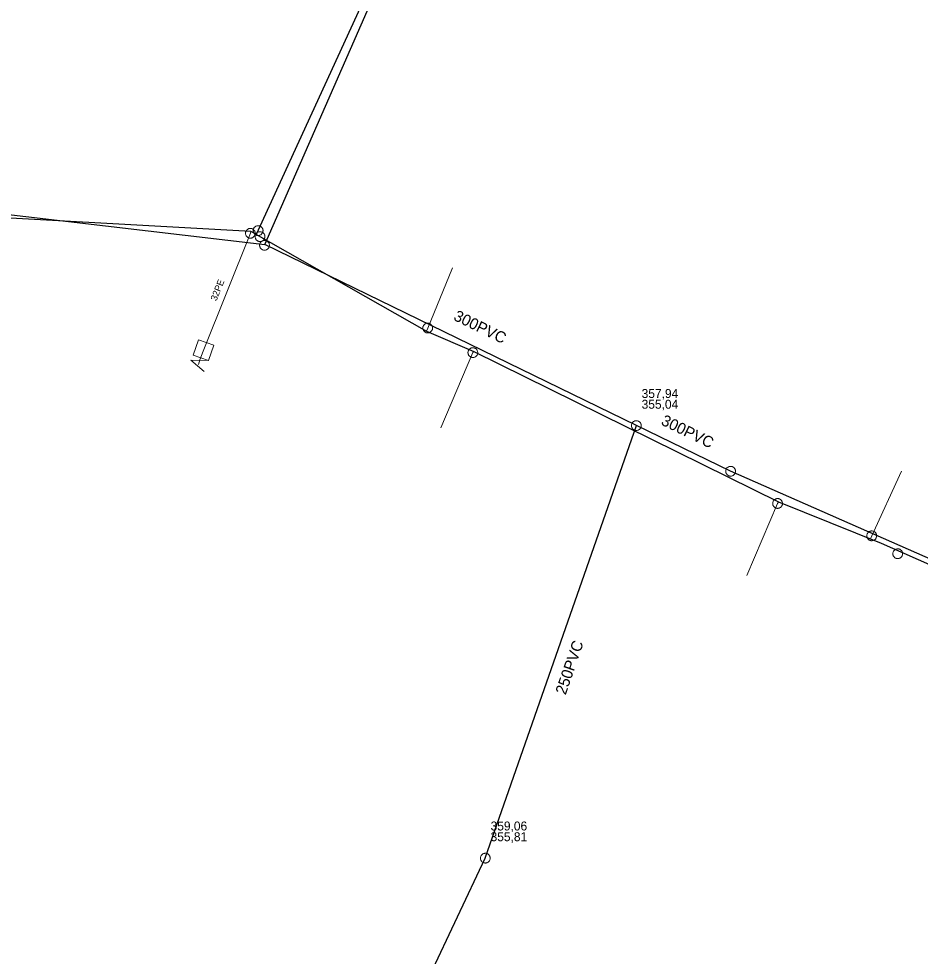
# Model space of a CAD drawing. Extents: x -741806 to -738704, y -1059275 to -1055387.
# Drawn here: x -740647.7 to -740567.1, y -1058133.8 to -1058050 of the extents above; entities that cross this region are included whole.
import ezdxf

# ---------------------------------------------------------------- set-up
doc = ezdxf.new("R2010")
doc.units = 0
doc.header["$LTSCALE"] = 0.4
for name, color, linetype, lineweight in [('2', 7, 'Continuous', 25), ('21', 7, 'Continuous', 13), ('3', 7, 'Continuous', 13), ('51', 7, 'Continuous', 13), ('52', 7, 'Continuous', 25), ('6', 7, 'Continuous', 13), ('60', 7, 'Continuous', 13)]:
    doc.layers.add(name, color=color, linetype=linetype, lineweight=lineweight)
doc.layers.add('5', color=7, linetype='Continuous')
doc.layers.add('54', color=7, linetype='Continuous')

msp = doc.modelspace()

# ---------------------------------------------------------------- linework, layer by layer
at = {"layer": '2'}
for p, q in [((-740584.07, -1058090.47), (-740592.5, -1058086.389)), ((-740538.35, -1058110.56), (-740584.07, -1058090.47))]:
    msp.add_line(p, q, dxfattribs=at)
for points in [[(-740592.5, -1058086.389), (-740625.71, -1058070.179), (-740593.93, -1057997.629)], [(-740824.89, -1058051.27), (-740778.35, -1058055.46), (-740728.07, -1058059.94), (-740708.829, -1058061.48), (-740678.949, -1058063.95), (-740625.71, -1058070.179)], [(-740583.26, -1058185.25), (-740598.636, -1058178.666), (-740610.313, -1058173.665), (-740625.809, -1058167.03), (-740606.009, -1058125.064), (-740592.5, -1058086.389)]]:
    msp.add_lwpolyline(points, dxfattribs=at)
at = {"layer": '21'}
for points in [[(-740626.965, -1058069.033), (-740627.02, -1058069.19), (-740631.25, -1058079.72), (-740631.527, -1058080.499), (-740631.654, -1058080.922)], [(-740611.274, -1058077.928), (-740611.16, -1058077.659), (-740608.947, -1058072.284)], [(-740607.048, -1058079.747), (-740607.12, -1058079.86), (-740609.973, -1058086.591)], [(-740571.566, -1058096.51), (-740571.449, -1058096.24), (-740568.795, -1058090.463)], [(-740579.795, -1058093.213), (-740579.87, -1058093.35), (-740582.627, -1058099.791)]]:
    msp.add_lwpolyline(points, dxfattribs=at)
at = {"layer": '3'}
for points in [[(-740625.317, -1058070.31), (-740625.315, -1058070.265), (-740625.317, -1058070.22), (-740625.324, -1058070.174), (-740625.336, -1058070.13), (-740625.352, -1058070.087), (-740625.373, -1058070.046), (-740625.398, -1058070.008), (-740625.426, -1058069.971), (-740625.459, -1058069.94), (-740625.494, -1058069.911), (-740625.533, -1058069.885), (-740625.574, -1058069.864), (-740625.616, -1058069.848), (-740625.66, -1058069.835), (-740625.705, -1058069.829), (-740625.751, -1058069.826), (-740625.797, -1058069.829), (-740625.842, -1058069.835), (-740625.887, -1058069.847), (-740625.93, -1058069.864), (-740625.97, -1058069.884), (-740626.008, -1058069.908), (-740626.044, -1058069.938), (-740626.077, -1058069.969), (-740626.106, -1058070.005), (-740626.13, -1058070.044), (-740626.152, -1058070.084), (-740626.168, -1058070.127), (-740626.18, -1058070.171), (-740626.187, -1058070.217), (-740626.19, -1058070.262), (-740626.188, -1058070.307), (-740626.181, -1058070.353), (-740626.169, -1058070.398), (-740626.153, -1058070.44), (-740626.132, -1058070.481), (-740626.107, -1058070.519), (-740626.078, -1058070.556), (-740626.046, -1058070.587), (-740626.011, -1058070.616), (-740625.973, -1058070.642), (-740625.932, -1058070.663), (-740625.889, -1058070.68), (-740625.845, -1058070.692), (-740625.8, -1058070.698), (-740625.754, -1058070.701), (-740625.708, -1058070.699), (-740625.663, -1058070.692), (-740625.619, -1058070.68), (-740625.576, -1058070.663), (-740625.535, -1058070.643), (-740625.496, -1058070.619), (-740625.461, -1058070.589), (-740625.428, -1058070.558), (-740625.399, -1058070.522), (-740625.374, -1058070.483), (-740625.354, -1058070.443), (-740625.337, -1058070.4), (-740625.325, -1058070.356), (-740625.317, -1058070.311)], [(-740592.894, -1058086.197), (-740592.91, -1058086.239), (-740592.924, -1058086.283), (-740592.933, -1058086.328), (-740592.936, -1058086.373), (-740592.935, -1058086.419), (-740592.93, -1058086.465), (-740592.919, -1058086.509), (-740592.905, -1058086.553), (-740592.884, -1058086.594), (-740592.861, -1058086.633), (-740592.833, -1058086.67), (-740592.802, -1058086.704), (-740592.767, -1058086.733), (-740592.73, -1058086.76), (-740592.69, -1058086.781), (-740592.647, -1058086.8), (-740592.603, -1058086.812), (-740592.559, -1058086.821), (-740592.513, -1058086.825), (-740592.467, -1058086.824), (-740592.422, -1058086.818), (-740592.378, -1058086.808), (-740592.334, -1058086.792), (-740592.293, -1058086.774), (-740592.253, -1058086.749), (-740592.217, -1058086.721), (-740592.184, -1058086.691), (-740592.153, -1058086.656), (-740592.127, -1058086.618), (-740592.105, -1058086.578), (-740592.088, -1058086.536), (-740592.074, -1058086.493), (-740592.066, -1058086.447), (-740592.062, -1058086.401), (-740592.063, -1058086.356), (-740592.068, -1058086.31), (-740592.079, -1058086.266), (-740592.094, -1058086.222), (-740592.114, -1058086.181), (-740592.137, -1058086.142), (-740592.165, -1058086.106), (-740592.196, -1058086.072), (-740592.23, -1058086.042), (-740592.268, -1058086.016), (-740592.308, -1058085.994), (-740592.351, -1058085.976), (-740592.394, -1058085.962), (-740592.439, -1058085.954), (-740592.485, -1058085.95), (-740592.531, -1058085.951), (-740592.576, -1058085.957), (-740592.621, -1058085.967), (-740592.664, -1058085.983), (-740592.706, -1058086.002), (-740592.745, -1058086.026), (-740592.782, -1058086.054), (-740592.814, -1058086.084), (-740592.845, -1058086.12), (-740592.871, -1058086.157), (-740592.893, -1058086.196)], [(-740584.47, -1058090.293), (-740584.486, -1058090.335), (-740584.497, -1058090.379), (-740584.504, -1058090.425), (-740584.507, -1058090.47), (-740584.504, -1058090.516), (-740584.497, -1058090.562), (-740584.484, -1058090.606), (-740584.468, -1058090.649), (-740584.447, -1058090.689), (-740584.422, -1058090.727), (-740584.393, -1058090.763), (-740584.36, -1058090.796), (-740584.324, -1058090.823), (-740584.286, -1058090.849), (-740584.245, -1058090.869), (-740584.202, -1058090.886), (-740584.158, -1058090.897), (-740584.113, -1058090.904), (-740584.067, -1058090.906), (-740584.021, -1058090.903), (-740583.976, -1058090.896), (-740583.933, -1058090.884), (-740583.889, -1058090.867), (-740583.849, -1058090.847), (-740583.81, -1058090.821), (-740583.775, -1058090.792), (-740583.743, -1058090.76), (-740583.714, -1058090.724), (-740583.689, -1058090.685), (-740583.669, -1058090.644), (-740583.653, -1058090.602), (-740583.641, -1058090.558), (-740583.634, -1058090.512), (-740583.632, -1058090.466), (-740583.634, -1058090.421), (-740583.641, -1058090.375), (-740583.654, -1058090.332), (-740583.671, -1058090.288), (-740583.692, -1058090.248), (-740583.716, -1058090.21), (-740583.745, -1058090.174), (-740583.778, -1058090.142), (-740583.813, -1058090.113), (-740583.852, -1058090.088), (-740583.893, -1058090.068), (-740583.936, -1058090.051), (-740583.98, -1058090.04), (-740584.025, -1058090.033), (-740584.071, -1058090.031), (-740584.117, -1058090.034), (-740584.162, -1058090.042), (-740584.206, -1058090.053), (-740584.249, -1058090.07), (-740584.29, -1058090.09), (-740584.328, -1058090.116), (-740584.364, -1058090.145), (-740584.395, -1058090.177), (-740584.425, -1058090.214), (-740584.449, -1058090.252), (-740584.47, -1058090.292)], [(-740605.821, -1058124.668), (-740605.863, -1058124.651), (-740605.907, -1058124.638), (-740605.953, -1058124.63), (-740605.997, -1058124.626), (-740606.043, -1058124.628), (-740606.089, -1058124.634), (-740606.133, -1058124.645), (-740606.177, -1058124.66), (-740606.218, -1058124.681), (-740606.256, -1058124.704), (-740606.293, -1058124.732), (-740606.327, -1058124.764), (-740606.355, -1058124.799), (-740606.382, -1058124.836), (-740606.403, -1058124.877), (-740606.421, -1058124.92), (-740606.433, -1058124.964), (-740606.442, -1058125.008), (-740606.445, -1058125.054), (-740606.443, -1058125.1), (-740606.437, -1058125.146), (-740606.427, -1058125.189), (-740606.411, -1058125.233), (-740606.392, -1058125.274), (-740606.367, -1058125.313), (-740606.338, -1058125.349), (-740606.308, -1058125.382), (-740606.272, -1058125.412), (-740606.234, -1058125.438), (-740606.194, -1058125.459), (-740606.152, -1058125.477), (-740606.108, -1058125.49), (-740606.063, -1058125.498), (-740606.016, -1058125.501), (-740605.972, -1058125.5), (-740605.926, -1058125.494), (-740605.882, -1058125.483), (-740605.838, -1058125.467), (-740605.798, -1058125.447), (-740605.759, -1058125.424), (-740605.722, -1058125.395), (-740605.689, -1058125.364), (-740605.659, -1058125.329), (-740605.633, -1058125.291), (-740605.612, -1058125.251), (-740605.594, -1058125.208), (-740605.581, -1058125.164), (-740605.573, -1058125.12), (-740605.57, -1058125.073), (-740605.572, -1058125.027), (-740605.578, -1058124.982), (-740605.588, -1058124.938), (-740605.604, -1058124.895), (-740605.624, -1058124.854), (-740605.648, -1058124.814), (-740605.676, -1058124.778), (-740605.708, -1058124.746), (-740605.743, -1058124.715), (-740605.781, -1058124.69), (-740605.82, -1058124.668)]]:
    msp.add_lwpolyline(points, dxfattribs=at)
at = {"layer": '51'}
for points in [[(-740626.583, -1058069.19), (-740626.585, -1058069.145), (-740626.592, -1058069.1), (-740626.604, -1058069.055), (-740626.62, -1058069.013), (-740626.641, -1058068.972), (-740626.666, -1058068.933), (-740626.695, -1058068.898), (-740626.727, -1058068.865), (-740626.763, -1058068.837), (-740626.801, -1058068.812), (-740626.842, -1058068.791), (-740626.885, -1058068.774), (-740626.929, -1058068.762), (-740626.974, -1058068.755), (-740627.02, -1058068.753), (-740627.066, -1058068.755), (-740627.111, -1058068.762), (-740627.155, -1058068.774), (-740627.198, -1058068.791), (-740627.239, -1058068.812), (-740627.277, -1058068.837), (-740627.313, -1058068.865), (-740627.345, -1058068.898), (-740627.374, -1058068.933), (-740627.399, -1058068.972), (-740627.42, -1058069.013), (-740627.436, -1058069.055), (-740627.448, -1058069.1), (-740627.455, -1058069.145), (-740627.458, -1058069.191), (-740627.455, -1058069.236), (-740627.448, -1058069.281), (-740627.436, -1058069.326), (-740627.42, -1058069.368), (-740627.399, -1058069.409), (-740627.374, -1058069.448), (-740627.345, -1058069.483), (-740627.313, -1058069.516), (-740627.277, -1058069.544), (-740627.239, -1058069.569), (-740627.198, -1058069.59), (-740627.155, -1058069.607), (-740627.111, -1058069.618), (-740627.066, -1058069.626), (-740627.02, -1058069.628), (-740626.974, -1058069.626), (-740626.929, -1058069.618), (-740626.885, -1058069.607), (-740626.842, -1058069.59), (-740626.801, -1058069.569), (-740626.763, -1058069.544), (-740626.727, -1058069.516), (-740626.695, -1058069.483), (-740626.666, -1058069.448), (-740626.641, -1058069.409), (-740626.62, -1058069.368), (-740626.604, -1058069.326), (-740626.592, -1058069.281), (-740626.585, -1058069.236), (-740626.583, -1058069.191)], [(-740626.519, -1058069.341), (-740626.477, -1058069.359), (-740626.434, -1058069.373), (-740626.388, -1058069.382), (-740626.344, -1058069.386), (-740626.298, -1058069.386), (-740626.251, -1058069.381), (-740626.207, -1058069.37), (-740626.163, -1058069.356), (-740626.122, -1058069.337), (-740626.083, -1058069.314), (-740626.046, -1058069.286), (-740626.012, -1058069.255), (-740625.981, -1058069.221), (-740625.955, -1058069.184), (-740625.933, -1058069.144), (-740625.914, -1058069.102), (-740625.9, -1058069.058), (-740625.891, -1058069.014), (-740625.887, -1058068.968), (-740625.888, -1058068.922), (-740625.893, -1058068.876), (-740625.902, -1058068.832), (-740625.918, -1058068.788), (-740625.936, -1058068.747), (-740625.96, -1058068.707), (-740625.987, -1058068.67), (-740626.018, -1058068.637), (-740626.053, -1058068.606), (-740626.09, -1058068.58), (-740626.13, -1058068.557), (-740626.171, -1058068.539), (-740626.215, -1058068.526), (-740626.26, -1058068.516), (-740626.305, -1058068.512), (-740626.351, -1058068.512), (-740626.397, -1058068.517), (-740626.442, -1058068.528), (-740626.485, -1058068.542), (-740626.526, -1058068.562), (-740626.566, -1058068.584), (-740626.603, -1058068.612), (-740626.637, -1058068.643), (-740626.667, -1058068.677), (-740626.694, -1058068.714), (-740626.716, -1058068.754), (-740626.735, -1058068.796), (-740626.748, -1058068.84), (-740626.757, -1058068.884), (-740626.761, -1058068.931), (-740626.761, -1058068.977), (-740626.755, -1058069.022), (-740626.746, -1058069.066), (-740626.731, -1058069.11), (-740626.713, -1058069.151), (-740626.689, -1058069.191), (-740626.661, -1058069.228), (-740626.631, -1058069.261), (-740626.596, -1058069.292), (-740626.559, -1058069.318), (-740626.519, -1058069.34)], [(-740625.716, -1058069.504), (-740625.716, -1058069.459), (-740625.722, -1058069.413), (-740625.732, -1058069.368), (-740625.747, -1058069.326), (-740625.766, -1058069.284), (-740625.79, -1058069.244), (-740625.818, -1058069.208), (-740625.849, -1058069.174), (-740625.884, -1058069.145), (-740625.921, -1058069.119), (-740625.961, -1058069.096), (-740626.004, -1058069.078), (-740626.047, -1058069.064), (-740626.092, -1058069.056), (-740626.138, -1058069.052), (-740626.184, -1058069.053), (-740626.229, -1058069.058), (-740626.273, -1058069.069), (-740626.317, -1058069.084), (-740626.359, -1058069.104), (-740626.398, -1058069.128), (-740626.434, -1058069.154), (-740626.468, -1058069.186), (-740626.498, -1058069.22), (-740626.524, -1058069.258), (-740626.546, -1058069.299), (-740626.564, -1058069.34), (-740626.577, -1058069.385), (-740626.586, -1058069.429), (-740626.59, -1058069.475), (-740626.589, -1058069.52), (-740626.583, -1058069.566), (-740626.573, -1058069.611), (-740626.558, -1058069.653), (-740626.539, -1058069.695), (-740626.515, -1058069.735), (-740626.487, -1058069.771), (-740626.456, -1058069.805), (-740626.421, -1058069.834), (-740626.384, -1058069.86), (-740626.344, -1058069.883), (-740626.301, -1058069.901), (-740626.258, -1058069.914), (-740626.213, -1058069.923), (-740626.167, -1058069.927), (-740626.121, -1058069.926), (-740626.076, -1058069.92), (-740626.032, -1058069.91), (-740625.988, -1058069.895), (-740625.946, -1058069.875), (-740625.908, -1058069.851), (-740625.871, -1058069.825), (-740625.838, -1058069.793), (-740625.807, -1058069.759), (-740625.781, -1058069.721), (-740625.759, -1058069.68), (-740625.741, -1058069.639), (-740625.728, -1058069.594), (-740625.719, -1058069.55), (-740625.716, -1058069.505)], [(-740610.723, -1058077.659), (-740610.725, -1058077.614), (-740610.732, -1058077.569), (-740610.744, -1058077.524), (-740610.76, -1058077.482), (-740610.781, -1058077.441), (-740610.806, -1058077.402), (-740610.835, -1058077.367), (-740610.867, -1058077.334), (-740610.903, -1058077.306), (-740610.941, -1058077.281), (-740610.982, -1058077.26), (-740611.025, -1058077.243), (-740611.069, -1058077.231), (-740611.114, -1058077.224), (-740611.16, -1058077.222), (-740611.206, -1058077.224), (-740611.251, -1058077.231), (-740611.295, -1058077.243), (-740611.338, -1058077.26), (-740611.379, -1058077.281), (-740611.417, -1058077.306), (-740611.453, -1058077.334), (-740611.485, -1058077.367), (-740611.514, -1058077.402), (-740611.539, -1058077.441), (-740611.56, -1058077.482), (-740611.576, -1058077.524), (-740611.588, -1058077.569), (-740611.595, -1058077.614), (-740611.598, -1058077.66), (-740611.595, -1058077.705), (-740611.588, -1058077.75), (-740611.576, -1058077.795), (-740611.56, -1058077.837), (-740611.539, -1058077.878), (-740611.514, -1058077.917), (-740611.485, -1058077.952), (-740611.453, -1058077.985), (-740611.417, -1058078.013), (-740611.379, -1058078.038), (-740611.338, -1058078.059), (-740611.295, -1058078.076), (-740611.251, -1058078.087), (-740611.206, -1058078.095), (-740611.16, -1058078.097), (-740611.114, -1058078.095), (-740611.069, -1058078.087), (-740611.025, -1058078.076), (-740610.982, -1058078.059), (-740610.941, -1058078.038), (-740610.903, -1058078.013), (-740610.867, -1058077.985), (-740610.835, -1058077.952), (-740610.806, -1058077.917), (-740610.781, -1058077.878), (-740610.76, -1058077.837), (-740610.744, -1058077.795), (-740610.732, -1058077.75), (-740610.725, -1058077.705), (-740610.723, -1058077.66)], [(-740606.718, -1058080.033), (-740606.702, -1058079.991), (-740606.691, -1058079.947), (-740606.684, -1058079.901), (-740606.682, -1058079.856), (-740606.685, -1058079.81), (-740606.693, -1058079.764), (-740606.706, -1058079.72), (-740606.722, -1058079.677), (-740606.744, -1058079.637), (-740606.769, -1058079.599), (-740606.798, -1058079.564), (-740606.831, -1058079.531), (-740606.867, -1058079.503), (-740606.905, -1058079.479), (-740606.947, -1058079.459), (-740606.99, -1058079.442), (-740607.034, -1058079.431), (-740607.079, -1058079.424), (-740607.125, -1058079.423), (-740607.171, -1058079.426), (-740607.216, -1058079.434), (-740607.26, -1058079.446), (-740607.303, -1058079.463), (-740607.343, -1058079.484), (-740607.382, -1058079.51), (-740607.417, -1058079.539), (-740607.448, -1058079.571), (-740607.477, -1058079.608), (-740607.501, -1058079.647), (-740607.522, -1058079.688), (-740607.537, -1058079.73), (-740607.549, -1058079.774), (-740607.556, -1058079.82), (-740607.557, -1058079.865), (-740607.554, -1058079.911), (-740607.547, -1058079.957), (-740607.534, -1058080), (-740607.518, -1058080.043), (-740607.496, -1058080.083), (-740607.471, -1058080.121), (-740607.441, -1058080.157), (-740607.409, -1058080.19), (-740607.373, -1058080.217), (-740607.334, -1058080.242), (-740607.293, -1058080.262), (-740607.25, -1058080.279), (-740607.205, -1058080.289), (-740607.161, -1058080.296), (-740607.114, -1058080.298), (-740607.069, -1058080.295), (-740607.024, -1058080.287), (-740606.98, -1058080.275), (-740606.937, -1058080.258), (-740606.897, -1058080.237), (-740606.858, -1058080.211), (-740606.823, -1058080.182), (-740606.791, -1058080.149), (-740606.763, -1058080.113), (-740606.738, -1058080.074), (-740606.719, -1058080.034)], [(-740580.08, -1058093.733), (-740580.039, -1058093.752), (-740579.997, -1058093.768), (-740579.951, -1058093.779), (-740579.907, -1058093.785), (-740579.861, -1058093.786), (-740579.814, -1058093.783), (-740579.77, -1058093.775), (-740579.726, -1058093.762), (-740579.684, -1058093.744), (-740579.644, -1058093.723), (-740579.605, -1058093.697), (-740579.57, -1058093.667), (-740579.538, -1058093.635), (-740579.51, -1058093.598), (-740579.487, -1058093.559), (-740579.466, -1058093.518), (-740579.451, -1058093.475), (-740579.44, -1058093.431), (-740579.434, -1058093.385), (-740579.433, -1058093.339), (-740579.437, -1058093.293), (-740579.444, -1058093.248), (-740579.458, -1058093.204), (-740579.475, -1058093.162), (-740579.497, -1058093.121), (-740579.523, -1058093.083), (-740579.552, -1058093.049), (-740579.585, -1058093.017), (-740579.622, -1058092.989), (-740579.66, -1058092.965), (-740579.701, -1058092.946), (-740579.744, -1058092.93), (-740579.789, -1058092.919), (-740579.834, -1058092.913), (-740579.88, -1058092.912), (-740579.926, -1058092.915), (-740579.971, -1058092.923), (-740580.015, -1058092.936), (-740580.057, -1058092.954), (-740580.097, -1058092.975), (-740580.135, -1058093.001), (-740580.171, -1058093.031), (-740580.202, -1058093.064), (-740580.23, -1058093.1), (-740580.254, -1058093.139), (-740580.274, -1058093.18), (-740580.289, -1058093.224), (-740580.301, -1058093.267), (-740580.306, -1058093.313), (-740580.308, -1058093.359), (-740580.304, -1058093.405), (-740580.297, -1058093.45), (-740580.283, -1058093.494), (-740580.266, -1058093.536), (-740580.244, -1058093.577), (-740580.218, -1058093.615), (-740580.189, -1058093.649), (-740580.155, -1058093.681), (-740580.119, -1058093.709), (-740580.081, -1058093.732)], [(-740571.012, -1058096.24), (-740571.014, -1058096.195), (-740571.021, -1058096.15), (-740571.033, -1058096.105), (-740571.049, -1058096.063), (-740571.07, -1058096.022), (-740571.095, -1058095.983), (-740571.124, -1058095.948), (-740571.156, -1058095.915), (-740571.192, -1058095.887), (-740571.23, -1058095.862), (-740571.271, -1058095.841), (-740571.314, -1058095.824), (-740571.358, -1058095.812), (-740571.403, -1058095.805), (-740571.449, -1058095.803), (-740571.495, -1058095.805), (-740571.54, -1058095.812), (-740571.584, -1058095.824), (-740571.627, -1058095.841), (-740571.668, -1058095.862), (-740571.706, -1058095.887), (-740571.742, -1058095.915), (-740571.774, -1058095.948), (-740571.803, -1058095.983), (-740571.828, -1058096.022), (-740571.849, -1058096.063), (-740571.865, -1058096.105), (-740571.877, -1058096.15), (-740571.884, -1058096.195), (-740571.887, -1058096.241), (-740571.884, -1058096.286), (-740571.877, -1058096.331), (-740571.865, -1058096.376), (-740571.849, -1058096.418), (-740571.828, -1058096.459), (-740571.803, -1058096.498), (-740571.774, -1058096.533), (-740571.742, -1058096.566), (-740571.706, -1058096.594), (-740571.668, -1058096.619), (-740571.627, -1058096.64), (-740571.584, -1058096.657), (-740571.54, -1058096.668), (-740571.495, -1058096.676), (-740571.449, -1058096.678), (-740571.403, -1058096.676), (-740571.358, -1058096.668), (-740571.314, -1058096.657), (-740571.271, -1058096.64), (-740571.23, -1058096.619), (-740571.192, -1058096.594), (-740571.156, -1058096.566), (-740571.124, -1058096.533), (-740571.095, -1058096.498), (-740571.07, -1058096.459), (-740571.049, -1058096.418), (-740571.033, -1058096.376), (-740571.021, -1058096.331), (-740571.014, -1058096.286), (-740571.012, -1058096.241)], [(-740568.69, -1058097.842), (-740568.691, -1058097.797), (-740568.699, -1058097.752), (-740568.711, -1058097.707), (-740568.727, -1058097.665), (-740568.748, -1058097.624), (-740568.772, -1058097.585), (-740568.802, -1058097.55), (-740568.834, -1058097.517), (-740568.87, -1058097.489), (-740568.907, -1058097.464), (-740568.949, -1058097.443), (-740568.992, -1058097.426), (-740569.036, -1058097.414), (-740569.081, -1058097.407), (-740569.127, -1058097.405), (-740569.173, -1058097.407), (-740569.218, -1058097.414), (-740569.262, -1058097.426), (-740569.304, -1058097.443), (-740569.346, -1058097.464), (-740569.384, -1058097.489), (-740569.419, -1058097.517), (-740569.451, -1058097.55), (-740569.481, -1058097.585), (-740569.505, -1058097.624), (-740569.527, -1058097.665), (-740569.543, -1058097.707), (-740569.554, -1058097.752), (-740569.562, -1058097.797), (-740569.565, -1058097.843), (-740569.562, -1058097.888), (-740569.554, -1058097.933), (-740569.543, -1058097.978), (-740569.527, -1058098.02), (-740569.505, -1058098.061), (-740569.481, -1058098.1), (-740569.451, -1058098.135), (-740569.419, -1058098.168), (-740569.384, -1058098.196), (-740569.346, -1058098.221), (-740569.304, -1058098.242), (-740569.262, -1058098.259), (-740569.218, -1058098.27), (-740569.173, -1058098.278), (-740569.127, -1058098.28), (-740569.081, -1058098.278), (-740569.036, -1058098.27), (-740568.992, -1058098.259), (-740568.949, -1058098.242), (-740568.907, -1058098.221), (-740568.87, -1058098.196), (-740568.834, -1058098.168), (-740568.802, -1058098.135), (-740568.772, -1058098.1), (-740568.748, -1058098.061), (-740568.727, -1058098.02), (-740568.711, -1058097.978), (-740568.699, -1058097.933), (-740568.691, -1058097.888), (-740568.69, -1058097.843)]]:
    msp.add_lwpolyline(points, dxfattribs=at)
at = {"layer": '52'}
for points in [[(-740489.868, -1057679.99), (-740497.519, -1057704.287), (-740502.89, -1057727.946), (-740504.09, -1057731.52), (-740504.16, -1057731.78), (-740504.295, -1057732.394), (-740505.458, -1057737.884), (-740512.487, -1057766.415), (-740507.033, -1057770.061), (-740517.328, -1057816.22), (-740521.664, -1057829.6), (-740544.85, -1057893.509), (-740554.399, -1057919.446), (-740570.451, -1057950.712), (-740592.697, -1058007.398), (-740600.714, -1058010.487), (-740613.05, -1058039.97), (-740626.485, -1058069.3)], [(-740626.537, -1058069.271), (-740626.965, -1058069.033), (-740656.548, -1058067.382), (-740672.59, -1058065.485), (-740708.822, -1058062.591), (-740710.671, -1058062.095), (-740751.42, -1058058.46), (-740773.993, -1058056.467), (-740779.522, -1058055.831), (-740794.666, -1058054.688), (-740823.883, -1058052.338), (-740835.024, -1058060.166), (-740841.695, -1058066.003), (-740887.96, -1058170.041), (-740903.829, -1058207.8), (-740906.75, -1058213.899)], [(-740626.537, -1058069.271), (-740611.274, -1058077.928), (-740607.048, -1058079.747), (-740579.795, -1058093.213), (-740570.602, -1058096.897), (-740532.225, -1058113.83), (-740517.855, -1058120.051), (-740513.324, -1058122.253), (-740504.39, -1058126.338), (-740503.699, -1058126.483), (-740502.37, -1058127.033), (-740486.897, -1058134.004), (-740457.162, -1058146.413), (-740443.484, -1058152.384), (-740427.182, -1058159.244), (-740419.138, -1058162.291), (-740410.995, -1058165.443), (-740391.353, -1058175.139), (-740386.026, -1058178.196), (-740381.706, -1058180.966), (-740367.603, -1058204.507), (-740360.942, -1058216.102), (-740348.353, -1058239.253)]]:
    msp.add_lwpolyline(points, dxfattribs=at)
at = {"layer": '60'}
msp.add_lwpolyline([(-740631.655, -1058078.711), (-740630.288, -1058079.199), (-740630.775, -1058080.567), (-740632.143, -1058080.079)], close=True, dxfattribs=at)
msp.add_lwpolyline([(-740630.793, -1058080.567), (-740632.336, -1058080.542), (-740631.141, -1058081.542)], dxfattribs=at)

# ---------------------------------------------------------------- texts
at = {"layer": '5'}
for s, rotation, p in [('300PVC', 334, (-740608.919, -1058076.911)), ('300PVC', 334, (-740590.368, -1058086.264)), ('250PVC', 71, (-740598.826, -1058110.522))]:
    msp.add_text(s, height=1, rotation=rotation, dxfattribs=at).set_placement(p)
at = {"layer": '54'}
msp.add_text('32PE', height=0.6, rotation=68, dxfattribs=at).set_placement((-740630.056, -1058075.288))
at = {"layer": '6'}
for s, p in [('357,94', (-740592.027, -1058083.916)), ('355,04', (-740592.027, -1058084.876)), ('359,06', (-740605.536, -1058122.59)), ('355,81', (-740605.536, -1058123.55))]:
    msp.add_text(s, height=0.8, dxfattribs=at).set_placement(p)

doc.saveas('drawing.dxf')
